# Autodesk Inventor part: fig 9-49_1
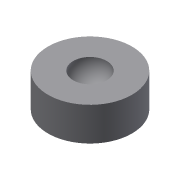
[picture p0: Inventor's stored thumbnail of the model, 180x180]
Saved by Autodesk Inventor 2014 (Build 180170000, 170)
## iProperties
Created: 2013-03
Part Number: fig 9-49_1
Material: Generic
Document SubType Name: Modeling
Designer: CADCIM
Density: 1 g/cm^3
Appearance: Default
Author: CADCIM
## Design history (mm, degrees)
sketch "Sketch1"
  geometry: C1 r 12.5 at (0, 0); 1 further point
  constraints: 1 centre point, 1 coincident
  dimensions: "d0" = 25 diameter of C1
extrude "Extrusion1" new body sketch "Sketch1" distance "d2" = 10; taper "d3" = 0 deg
sketch "Sketch2"
  geometry: L1 (12.5, 10)-(-12.5, 10) reference; L2 (-5, 10)-(5, 10); A1 r 5 centre (0, 10) between (-5, 10) and (5, 10); 1 further point
  constraints: 2 end point, 2 point on circle, 2 point on line, 1 centre point, 1 midpoint
  dimensions: "d4" = 10 diameter of A1
revolve "Revolution1" sketch "Sketch2" stored, may be unused: angle "d6" = 90 deg
body "Solid1"
